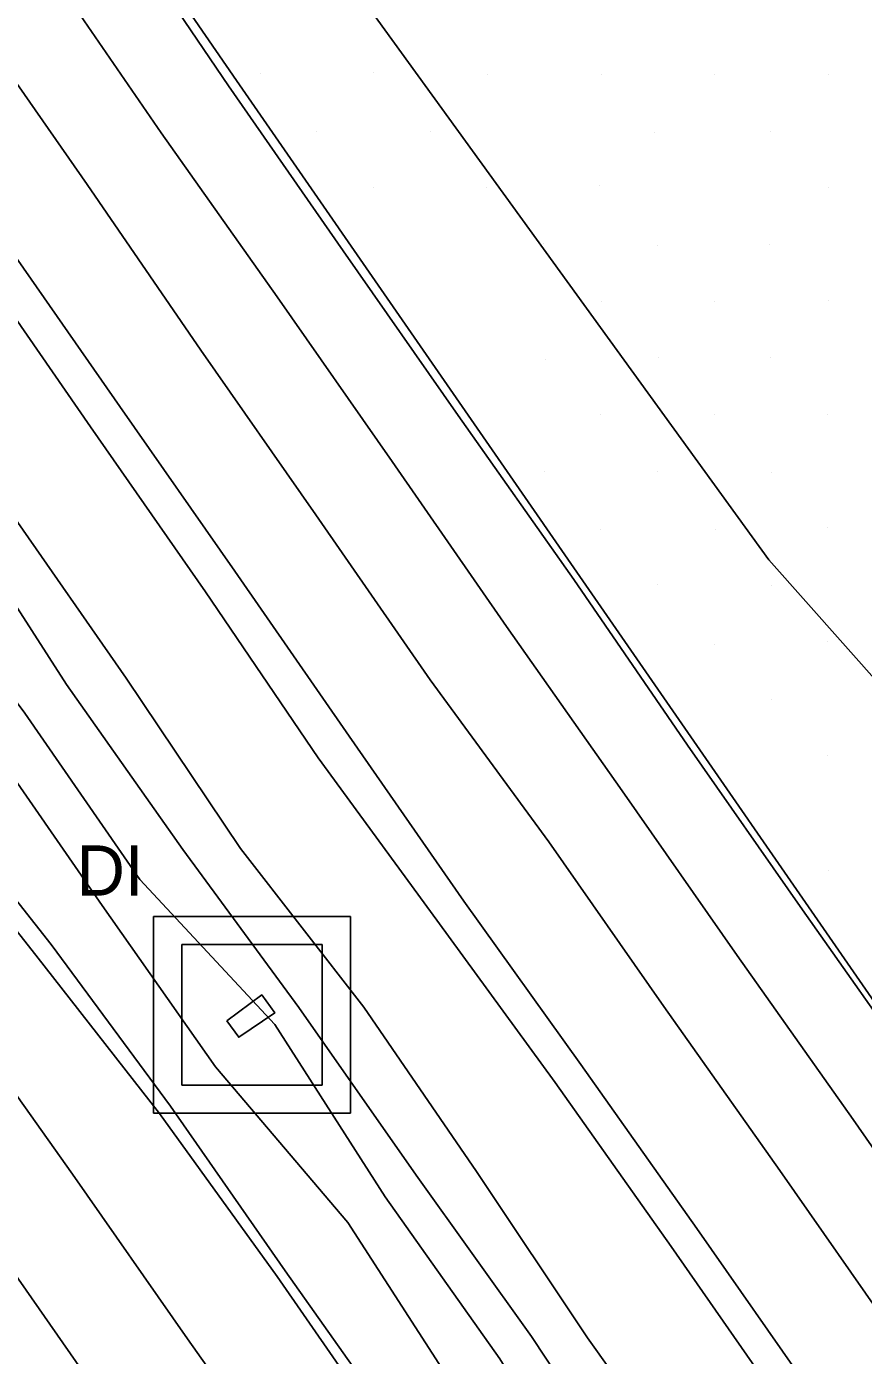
# Model space of a CAD drawing. Extents: x 1602514 to 1609837, y 863887 to 871157.
# Drawn here: x 1604945.1 to 1605049.2, y 867856.2 to 868021.6 of the extents above; entities that cross this region are included whole.
import ezdxf

# ---------------------------------------------------------------- set-up
doc = ezdxf.new("R2010")
doc.units = 0
for name, color, linetype in [('Drainage-Structures', 7, 'Continuous'), ('Survey-Centerline', 7, 'Continuous'), ('Survey-Edge of pavement', 7, 'Continuous'), ('Survey-Flow line', 7, 'Continuous'), ('Survey-Ridge Lines', 7, 'Continuous'), ('Survey-Safety', 7, 'Continuous'), ('Survey-Shoulders', 7, 'Continuous'), ('Survey-Spot dirt', 7, 'Continuous'), ('Survey-Vegetation trees', 7, 'Continuous')]:
    doc.layers.add(name, color=color, linetype=linetype)

msp = doc.modelspace()

# ---------------------------------------------------------------- linework, layer by layer
at = {"layer": 'Drainage-Structures'}
for p, q in [((1604960.87, 867910.81), (1604985.37, 867910.81)), ((1604960.87, 867886.31), (1604960.87, 867910.81)), ((1604960.87, 867910.81), (1604985.37, 867910.81)), ((1604960.87, 867886.31), (1604960.87, 867910.81)), ((1604985.37, 867910.81), (1604985.37, 867886.31)), ((1604985.37, 867910.81), (1604985.37, 867886.31)), ((1604964.37, 867907.31), (1604981.87, 867907.31)), ((1604964.37, 867889.81), (1604964.37, 867907.31)), ((1604964.37, 867907.31), (1604981.87, 867907.31)), ((1604964.37, 867889.81), (1604964.37, 867907.31)), ((1604981.87, 867907.31), (1604981.87, 867889.81)), ((1604981.87, 867907.31), (1604981.87, 867889.81)), ((1604981.87, 867889.81), (1604964.37, 867889.81)), ((1604981.87, 867889.81), (1604964.37, 867889.81)), ((1604985.37, 867886.31), (1604960.87, 867886.31)), ((1604985.37, 867886.31), (1604960.87, 867886.31))]:
    msp.add_line(p, q, dxfattribs=at)
at = {"layer": 'Survey-Centerline'}
for points in [[(1605053.13, 867858.7), (1605038.82, 867879.2), (1605024.38, 867899.6), (1605010.08, 867920.1), (1604995.31, 867940.28), (1604981.07, 867960.82), (1604966.76, 867981.32), (1604952.62, 868001.93), (1604938.31, 868022.43), (1604924.39, 868043.2), (1604910.21, 868063.78), (1604896.3, 868084.55), (1604883.6, 868103.92), (1604870.18, 868125.01), (1604856.33, 868145.82), (1604843.04, 868167)], [(1605053.13, 867858.7), (1605038.82, 867879.2), (1605024.38, 867899.6), (1605010.08, 867920.1), (1604995.31, 867940.28), (1604981.07, 867960.82), (1604966.76, 867981.32), (1604952.62, 868001.93), (1604938.31, 868022.43), (1604924.39, 868043.2), (1604910.21, 868063.78), (1604896.3, 868084.55), (1604883.6, 868103.92), (1604870.18, 868125.01), (1604856.33, 868145.82), (1604843.04, 868167)], [(1605011.74, 867768.84), (1604997.34, 867789.28), (1604983.04, 867809.77), (1604968.85, 867830.35), (1604954.41, 867850.76), (1604940.1, 867871.26), (1604925.6, 867891.62), (1604911.36, 867912.16), (1604897.05, 867932.66), (1604882.9, 867953.27), (1604868.6, 867973.76), (1604854.39, 867994.33), (1604840.21, 868014.92), (1604826.29, 868035.69), (1604811.67, 868058.15), (1604798.25, 868079.24), (1604784.66, 868100.23), (1604771.38, 868121.4), (1604757.96, 868142.49), (1604745.31, 868164.07)], [(1605011.74, 867768.84), (1604997.34, 867789.28), (1604983.04, 867809.77), (1604968.85, 867830.35), (1604954.41, 867850.76), (1604940.1, 867871.26), (1604925.6, 867891.62), (1604911.36, 867912.16), (1604897.05, 867932.66), (1604882.9, 867953.27), (1604868.6, 867973.76), (1604854.39, 867994.33), (1604840.21, 868014.92), (1604826.29, 868035.69), (1604811.67, 868058.15), (1604798.25, 868079.24), (1604784.66, 868100.23), (1604771.38, 868121.4), (1604757.96, 868142.49), (1604745.31, 868164.07)]]:
    msp.add_lwpolyline(points, dxfattribs=at)
at = {"layer": 'Survey-Edge of pavement'}
for points in [[(1605047.79, 867763.52), (1605033.48, 867784.02), (1605019.09, 867804.45), (1605004.78, 867824.95), (1604990.47, 867845.45), (1604976.24, 867866), (1604961.6, 867886.27), (1604946.22, 867906.01), (1604930.68, 867925.65), (1604914.84, 867945.08), (1604899.3, 867964.71), (1604883.46, 867984.14), (1604867.66, 868003.59), (1604852.31, 868023.36), (1604837.29, 868043.35), (1604821.71, 868064.54), (1604808.29, 868085.63), (1604795.07, 868106.85), (1604781.95, 868128.13), (1604768.7, 868149.33), (1604755.55, 868170.59)], [(1605047.79, 867763.52), (1605033.48, 867784.02), (1605019.09, 867804.45), (1605004.78, 867824.95), (1604990.47, 867845.45), (1604976.24, 867866), (1604961.6, 867886.27), (1604946.22, 867906.01), (1604930.68, 867925.65), (1604914.84, 867945.08), (1604899.3, 867964.71), (1604883.46, 867984.14), (1604867.66, 868003.59), (1604852.31, 868023.36), (1604837.29, 868043.35), (1604821.71, 868064.54), (1604808.29, 868085.63), (1604795.07, 868106.85), (1604781.95, 868128.13), (1604768.7, 868149.33), (1604755.55, 868170.59)], [(1604828.88, 868157.99), (1604842.17, 868136.82), (1604856.19, 868116.11), (1604869.61, 868095.02), (1604882.7, 868075.06), (1604896.39, 868054.13), (1604910.57, 868033.54), (1604924.48, 868012.78), (1604938.79, 867992.28), (1604953.03, 867971.74), (1604967.34, 867951.24), (1604981.36, 867930.54), (1604996.12, 867910.36), (1605010.85, 867890.16), (1605025.29, 867869.75), (1605039.59, 867849.25), (1605053.9, 867828.75)], [(1604828.88, 868157.99), (1604842.17, 868136.82), (1604856.19, 868116.11), (1604869.61, 868095.02), (1604882.7, 868075.06), (1604896.39, 868054.13), (1604910.57, 868033.54), (1604924.48, 868012.78), (1604938.79, 867992.28), (1604953.03, 867971.74), (1604967.34, 867951.24), (1604981.36, 867930.54), (1604996.12, 867910.36), (1605010.85, 867890.16), (1605025.29, 867869.75), (1605039.59, 867849.25), (1605053.9, 867828.75)], [(1605062.24, 867865.06), (1605047.94, 867885.56), (1605033.5, 867905.97), (1605019.19, 867926.46), (1605004.81, 867946.91), (1604990.57, 867967.45), (1604976.26, 867987.95), (1604961.82, 868008.36), (1604947.68, 868028.97), (1604933.57, 868049.6), (1604919.45, 868070.23), (1604905.86, 868091.23), (1604893.44, 868110.18), (1604879.75, 868131.1), (1604866.27, 868152.15)], [(1605062.24, 867865.06), (1605047.94, 867885.56), (1605033.5, 867905.97), (1605019.19, 867926.46), (1605004.81, 867946.91), (1604990.57, 867967.45), (1604976.26, 867987.95), (1604961.82, 868008.36), (1604947.68, 868028.97), (1604933.57, 868049.6), (1604919.45, 868070.23), (1604905.86, 868091.23), (1604893.44, 868110.18), (1604879.75, 868131.1), (1604866.27, 868152.15)]]:
    msp.add_lwpolyline(points, dxfattribs=at)
at = {"layer": 'Survey-Flow line'}
msp.add_line((1604959.15, 867915.43), (1604975.95, 867897.35), dxfattribs=at)
msp.add_line((1604959.15, 867915.43), (1604975.95, 867897.35), dxfattribs=at)
for points in [[(1604959.15, 867915.43), (1604944.85, 867936.1), (1604930.04, 867955.86), (1604918.09, 867978.38), (1604900.65, 867996.47), (1604888.29, 868018.24), (1604875.83, 868039.34), (1604861.33, 868059.03), (1604847.7, 868079.98), (1604832.28, 868099.3), (1604818.54, 868120.55), (1604807.37, 868142.39), (1604794.48, 868164.13)], [(1604959.15, 867915.43), (1604944.85, 867936.1), (1604930.04, 867955.86), (1604918.09, 867978.38), (1604900.65, 867996.47), (1604888.29, 868018.24), (1604875.83, 868039.34), (1604861.33, 868059.03), (1604847.7, 868079.98), (1604832.28, 868099.3), (1604818.54, 868120.55), (1604807.37, 868142.39), (1604794.48, 868164.13)], [(1605163.03, 867625.47), (1605146.71, 867650.36), (1605131.82, 867669.77), (1605118.18, 867691.27), (1605103.59, 867711.57), (1605090.72, 867733.07), (1605075.09, 867752.65), (1605061.03, 867772.8), (1605046.57, 867793.93), (1605031.66, 867813.78), (1605017.49, 867834.08), (1605003.98, 867855.76), (1604989.68, 867875.93), (1604975.95, 867897.35)], [(1605163.03, 867625.47), (1605146.71, 867650.36), (1605131.82, 867669.77), (1605118.18, 867691.27), (1605103.59, 867711.57), (1605090.72, 867733.07), (1605075.09, 867752.65), (1605061.03, 867772.8), (1605046.57, 867793.93), (1605031.66, 867813.78), (1605017.49, 867834.08), (1605003.98, 867855.76), (1604989.68, 867875.93), (1604975.95, 867897.35)]]:
    msp.add_lwpolyline(points, dxfattribs=at)
at = {"layer": 'Survey-Ridge Lines'}
for points in [[(1605051.65, 867797.5), (1605036.77, 867817.35), (1605022.01, 867837.19), (1605007.9, 867858.54), (1604993.54, 867878.63), (1604978.97, 867899.5), (1604964.5, 867919.14), (1604950.02, 867939.7), (1604936.69, 867960.42), (1604922.33, 867981.34), (1604908.6, 868001.96), (1604894.34, 868022.4), (1604880.3, 868042.34), (1604865.82, 868061.95), (1604851.26, 868082.3), (1604838.08, 868102.99), (1604825.98, 868125.37), (1604812.4, 868145.54), (1604798.82, 868166.89)], [(1605051.65, 867797.5), (1605036.77, 867817.35), (1605022.01, 867837.19), (1605007.9, 867858.54), (1604993.54, 867878.63), (1604978.97, 867899.5), (1604964.5, 867919.14), (1604950.02, 867939.7), (1604936.69, 867960.42), (1604922.33, 867981.34), (1604908.6, 868001.96), (1604894.34, 868022.4), (1604880.3, 868042.34), (1604865.82, 868061.95), (1604851.26, 868082.3), (1604838.08, 868102.99), (1604825.98, 868125.37), (1604812.4, 868145.54), (1604798.82, 868166.89)], [(1604832.76, 868160.46), (1604846.05, 868139.29), (1604859.54, 868118.24), (1604873.33, 868097.38), (1604886.31, 868077.58), (1604900.26, 868056.83), (1604914.18, 868036.07), (1604928.09, 868015.3), (1604942.4, 867994.8), (1604956.68, 867974.28), (1604970.98, 867953.78), (1604985.23, 867933.24), (1604999.5, 867912.72), (1605014.04, 867892.39), (1605028.48, 867871.98), (1605042.79, 867851.48), (1605057.1, 867830.99)], [(1604832.76, 868160.46), (1604846.05, 868139.29), (1604859.54, 868118.24), (1604873.33, 868097.38), (1604886.31, 868077.58), (1604900.26, 868056.83), (1604914.18, 868036.07), (1604928.09, 868015.3), (1604942.4, 867994.8), (1604956.68, 867974.28), (1604970.98, 867953.78), (1604985.23, 867933.24), (1604999.5, 867912.72), (1605014.04, 867892.39), (1605028.48, 867871.98), (1605042.79, 867851.48), (1605057.1, 867830.99)], [(1605053.34, 867767.54), (1605040.06, 867789.34), (1605025.74, 867809.65), (1605012.97, 867830.97), (1604998.49, 867851.89), (1604985.06, 867872.71), (1604968.57, 867892.09), (1604954.47, 867912.19), (1604940.14, 867932.81), (1604924.76, 867952.23), (1604909.86, 867972.64), (1604894.62, 867992.3), (1604881.05, 868013.25), (1604867.15, 868033.52), (1604851.96, 868052.93), (1604838.33, 868073.89), (1604821.72, 868092.58), (1604806.24, 868112.59), (1604793.33, 868133.58), (1604780.42, 868155.19)], [(1605053.34, 867767.54), (1605040.06, 867789.34), (1605025.74, 867809.65), (1605012.97, 867830.97), (1604998.49, 867851.89), (1604985.06, 867872.71), (1604968.57, 867892.09), (1604954.47, 867912.19), (1604940.14, 867932.81), (1604924.76, 867952.23), (1604909.86, 867972.64), (1604894.62, 867992.3), (1604881.05, 868013.25), (1604867.15, 868033.52), (1604851.96, 868052.93), (1604838.33, 868073.89), (1604821.72, 868092.58), (1604806.24, 868112.59), (1604793.33, 868133.58), (1604780.42, 868155.19)], [(1605036.55, 867755.68), (1605022.25, 867776.17), (1605008.1, 867796.78), (1604993.79, 867817.28), (1604979.55, 867837.82), (1604965.11, 867858.23), (1604950.8, 867878.73), (1604936.3, 867899.09), (1604922.03, 867919.61), (1604907.72, 867940.1), (1604893.57, 867960.71), (1604879.27, 867981.21), (1604864.8, 868001.6), (1604850.06, 868021.8), (1604836.15, 868042.57), (1604821.71, 868064.54)], [(1605036.55, 867755.68), (1605022.25, 867776.17), (1605008.1, 867796.78), (1604993.79, 867817.28), (1604979.55, 867837.82), (1604965.11, 867858.23), (1604950.8, 867878.73), (1604936.3, 867899.09), (1604922.03, 867919.61), (1604907.72, 867940.1), (1604893.57, 867960.71), (1604879.27, 867981.21), (1604864.8, 868001.6), (1604850.06, 868021.8), (1604836.15, 868042.57), (1604821.71, 868064.54)], [(1604970.01, 867897.84), (1604971.48, 867895.78), (1604975.96, 867898.8), (1604974.33, 867901.05), (1604970.01, 867897.84)], [(1604970.01, 867897.84), (1604971.48, 867895.78), (1604975.96, 867898.8), (1604974.33, 867901.05), (1604970.01, 867897.84)]]:
    msp.add_lwpolyline(points, dxfattribs=at)
at = {"layer": 'Survey-Safety'}
msp.add_lwpolyline([(1604890.49, 868133.93), (1604924.91, 868081.98), (1604971.18, 868014.88), (1605073.48, 867867.11), (1605156.28, 867749.05), (1605229.97, 867646.39)], dxfattribs=at)
msp.add_lwpolyline([(1604890.49, 868133.93), (1604924.91, 868081.98), (1604971.18, 868014.88), (1605073.48, 867867.11), (1605156.28, 867749.05), (1605229.97, 867646.39)], dxfattribs=at)
at = {"layer": 'Survey-Shoulders'}
for points in [[(1605056.06, 867891.23), (1605041.63, 867911.64), (1605027.32, 867932.14), (1605013.17, 867952.75), (1604998.77, 867973.17), (1604984.46, 867993.67), (1604970.18, 868014.19), (1604956.17, 868034.89), (1604941.96, 868055.46), (1604927.78, 868076.05), (1604913.86, 868096.82), (1604901.74, 868115.46), (1604888.32, 868136.55), (1604874.3, 868157.26)], [(1605056.06, 867891.23), (1605041.63, 867911.64), (1605027.32, 867932.14), (1605013.17, 867952.75), (1604998.77, 867973.17), (1604984.46, 867993.67), (1604970.18, 868014.19), (1604956.17, 868034.89), (1604941.96, 868055.46), (1604927.78, 868076.05), (1604913.86, 868096.82), (1604901.74, 868115.46), (1604888.32, 868136.55), (1604874.3, 868157.26)], [(1605049, 867764.37), (1605034.69, 867784.86), (1605020.3, 867805.3), (1605005.99, 867825.8), (1604991.68, 867846.29), (1604977.25, 867866.7), (1604962.97, 867887.22), (1604948.11, 867907.33), (1604932.6, 867926.99), (1604917.51, 867946.94), (1604902.29, 867966.8), (1604887.27, 867986.8), (1604871.85, 868006.52), (1604856.96, 868026.61), (1604842.49, 868046.99), (1604827.54, 868068.25), (1604812.61, 868088.38), (1604798.76, 868109.19), (1604785.47, 868130.37), (1604771.88, 868151.35)], [(1605049, 867764.37), (1605034.69, 867784.86), (1605020.3, 867805.3), (1605005.99, 867825.8), (1604991.68, 867846.29), (1604977.25, 867866.7), (1604962.97, 867887.22), (1604948.11, 867907.33), (1604932.6, 867926.99), (1604917.51, 867946.94), (1604902.29, 867966.8), (1604887.27, 867986.8), (1604871.85, 868006.52), (1604856.96, 868026.61), (1604842.49, 868046.99), (1604827.54, 868068.25), (1604812.61, 868088.38), (1604798.76, 868109.19), (1604785.47, 868130.37), (1604771.88, 868151.35)], [(1605058.81, 867797.58), (1605044.61, 867818.08), (1605029.4, 867838.01), (1605014.88, 867858.36), (1605001.06, 867879.09), (1604987.03, 867899.54), (1604971.7, 867919.27), (1604957.47, 867940.46), (1604943.31, 867960.82), (1604929.32, 867981.59), (1604915.32, 868002.25), (1604901.57, 868023.43), (1604887.96, 868044.21), (1604870.83, 868066.77), (1604857.7, 868087.44), (1604844.17, 868108.46), (1604830.62, 868129.47), (1604816.9, 868150.37)], [(1605058.81, 867797.58), (1605044.61, 867818.08), (1605029.4, 867838.01), (1605014.88, 867858.36), (1605001.06, 867879.09), (1604987.03, 867899.54), (1604971.7, 867919.27), (1604957.47, 867940.46), (1604943.31, 867960.82), (1604929.32, 867981.59), (1604915.32, 868002.25), (1604901.57, 868023.43), (1604887.96, 868044.21), (1604870.83, 868066.77), (1604857.7, 868087.44), (1604844.17, 868108.46), (1604830.62, 868129.47), (1604816.9, 868150.37)]]:
    msp.add_lwpolyline(points, dxfattribs=at)
at = {"layer": 'Survey-Spot dirt'}
for p, q in [((1604974.21, 868015.68), (1604974.21, 868015.68)), ((1604974.21, 868015.68), (1604974.21, 868015.68)), ((1604988.25, 868015.81), (1604988.25, 868015.81)), ((1604988.25, 868015.81), (1604988.25, 868015.81)), ((1605002.4, 868015.56), (1605002.4, 868015.56)), ((1605002.4, 868015.56), (1605002.4, 868015.56)), ((1605016.59, 868015.61), (1605016.59, 868015.61)), ((1605016.59, 868015.61), (1605016.59, 868015.61)), ((1605030.72, 868015.58), (1605030.72, 868015.58)), ((1605030.72, 868015.58), (1605030.72, 868015.58)), ((1605044.91, 868015.64), (1605044.91, 868015.64)), ((1605044.91, 868015.64), (1605044.91, 868015.64)), ((1604981.14, 868008.49), (1604981.14, 868008.49)), ((1604981.14, 868008.49), (1604981.14, 868008.49)), ((1604995.4, 868008.57), (1604995.4, 868008.57)), ((1604995.4, 868008.57), (1604995.4, 868008.57)), ((1605023.28, 868008.43), (1605023.28, 868008.43)), ((1605023.28, 868008.43), (1605023.28, 868008.43)), ((1605037.71, 868008.58), (1605037.71, 868008.58)), ((1605037.71, 868008.58), (1605037.71, 868008.58)), ((1604988.28, 868001.49), (1604988.28, 868001.49)), ((1604988.28, 868001.49), (1604988.28, 868001.49)), ((1605002.31, 868001.6), (1605002.31, 868001.6)), ((1605002.31, 868001.6), (1605002.31, 868001.6)), ((1605016.38, 868001.86), (1605016.38, 868001.86)), ((1605016.38, 868001.86), (1605016.38, 868001.86)), ((1605044.85, 868001.53), (1605044.85, 868001.53)), ((1605044.85, 868001.53), (1605044.85, 868001.53)), ((1605009.45, 867994.54), (1605009.45, 867994.54)), ((1605009.45, 867994.54), (1605009.45, 867994.54)), ((1605037.56, 867994.47), (1605037.56, 867994.47)), ((1605037.56, 867994.47), (1605037.56, 867994.47)), ((1605023.57, 867994.27), (1605023.57, 867994.27)), ((1605023.57, 867994.27), (1605023.57, 867994.27)), ((1605016.59, 867987.39), (1605016.59, 867987.39)), ((1605016.59, 867987.39), (1605016.59, 867987.39)), ((1605030.75, 867987.36), (1605030.75, 867987.36)), ((1605030.75, 867987.36), (1605030.75, 867987.36)), ((1605044.83, 867987.48), (1605044.83, 867987.48)), ((1605044.83, 867987.48), (1605044.83, 867987.48)), ((1605009.71, 867980.09), (1605009.71, 867980.09)), ((1605009.71, 867980.09), (1605009.71, 867980.09)), ((1605023.72, 867980.43), (1605023.72, 867980.43)), ((1605023.72, 867980.43), (1605023.72, 867980.43)), ((1605037.67, 867980.35), (1605037.67, 867980.35)), ((1605037.67, 867980.35), (1605037.67, 867980.35)), ((1605016.55, 867973.24), (1605016.55, 867973.24)), ((1605016.55, 867973.24), (1605016.55, 867973.24)), ((1605030.68, 867973.33), (1605030.68, 867973.33)), ((1605030.68, 867973.33), (1605030.68, 867973.33)), ((1605044.72, 867973.3), (1605044.72, 867973.3)), ((1605044.72, 867973.3), (1605044.72, 867973.3)), ((1605009.56, 867966.19), (1605009.56, 867966.19)), ((1605009.56, 867966.19), (1605009.56, 867966.19)), ((1605023.56, 867966.19), (1605023.56, 867966.19)), ((1605023.56, 867966.19), (1605023.56, 867966.19)), ((1605037.78, 867966.12), (1605037.78, 867966.12)), ((1605037.78, 867966.12), (1605037.78, 867966.12)), ((1605016.45, 867958.98), (1605016.45, 867958.98)), ((1605016.45, 867958.98), (1605016.45, 867958.98)), ((1605030.87, 867959.03), (1605030.87, 867959.03)), ((1605030.87, 867959.03), (1605030.87, 867959.03)), ((1605044.72, 867959.19), (1605044.72, 867959.19)), ((1605044.72, 867959.19), (1605044.72, 867959.19)), ((1605023.54, 867952.11), (1605023.54, 867952.11)), ((1605023.54, 867952.11), (1605023.54, 867952.11)), ((1605037.8, 867952.02), (1605037.8, 867952.02)), ((1605037.8, 867952.02), (1605037.8, 867952.02)), ((1605044.79, 867945.04), (1605044.79, 867945.04)), ((1605044.79, 867945.04), (1605044.79, 867945.04)), ((1605030.73, 867944.72), (1605030.73, 867944.72)), ((1605030.73, 867944.72), (1605030.73, 867944.72)), ((1605037.77, 867937.87), (1605037.77, 867937.87)), ((1605037.77, 867937.87), (1605037.77, 867937.87)), ((1605044.81, 867930.79), (1605044.81, 867930.79)), ((1605044.81, 867930.79), (1605044.81, 867930.79)), ((1605044.87, 867916.55), (1605044.87, 867916.55)), ((1605044.87, 867916.55), (1605044.87, 867916.55))]:
    msp.add_line(p, q, dxfattribs=at)
at = {"layer": 'Survey-Vegetation trees'}
msp.add_lwpolyline([(1604526.23, 869070.02), (1604587.99, 868903.85), (1604648.37, 868745.93), (1604701.9, 868632.63), (1604712.19, 868619.59), (1604746.5, 868500.11), (1604748.56, 868452.05), (1604792.9, 868384.62), (1604842.07, 868297.14), (1604881.2, 868202.42), (1604962.8, 868058.28), (1605037.44, 867955.22), (1605112.82, 867870.34), (1605164.26, 867779.29), (1605243.81, 867709), (1605352.92, 867776.98), (1605409.19, 867794.14), (1605453.11, 867683.59), (1605568.4, 867553.13), (1605652.11, 867437.78), (1605709.38, 867356.87), (1605792.64, 867252.16), (1605890.79, 867280.68)], dxfattribs=at)
msp.add_lwpolyline([(1604526.23, 869070.02), (1604587.99, 868903.85), (1604648.37, 868745.93), (1604701.9, 868632.63), (1604712.19, 868619.59), (1604746.5, 868500.11), (1604748.56, 868452.05), (1604792.9, 868384.62), (1604842.07, 868297.14), (1604881.2, 868202.42), (1604962.8, 868058.28), (1605037.44, 867955.22), (1605112.82, 867870.34), (1605164.26, 867779.29), (1605243.81, 867709), (1605352.92, 867776.98), (1605409.19, 867794.14), (1605453.11, 867683.59), (1605568.4, 867553.13), (1605652.11, 867437.78), (1605709.38, 867356.87), (1605792.64, 867252.16), (1605890.79, 867280.68)], dxfattribs=at)

# ---------------------------------------------------------------- texts
at = {"layer": 'Drainage-Structures'}
msp.add_text('DI', height=6.25, dxfattribs=at).set_placement((1604951.27, 867913.41))
msp.add_text('DI', height=6.25, dxfattribs=at).set_placement((1604951.27, 867913.41))

doc.saveas('drawing.dxf')
